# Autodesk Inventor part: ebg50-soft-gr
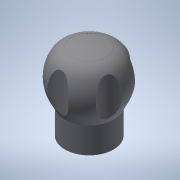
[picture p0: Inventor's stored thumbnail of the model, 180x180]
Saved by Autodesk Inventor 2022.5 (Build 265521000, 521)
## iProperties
Created: 2016-12
Part Number: ebg50-soft-gr
Material: 一般
Document SubType Name: Modeling
Designer: imaocorp
Density: 1 g/cm^3
Appearance: 既定
Author: imaocorp
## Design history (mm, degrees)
node "ebg50-soft-gr.x_t1"
node "ebg50-soft-gr"
node "Base1"
